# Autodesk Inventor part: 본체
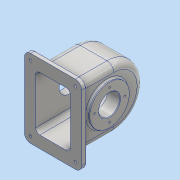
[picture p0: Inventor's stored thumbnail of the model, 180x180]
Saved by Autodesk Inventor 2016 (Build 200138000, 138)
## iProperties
Created: 2018-11
Part Number: 본체
Material: 알루미늄 6061
Document SubType Name: Modeling
Designer: user
Mass: 1091.9 g
Surface Area: 1182.65 cm^2
Volume: 404.407 cm^3
Density: 2.7 g/cm^3
Appearance: 알루미늄 - 평지
Author: user
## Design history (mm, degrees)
sketch "스케치1"
  geometry: L1 (55, 75)-(-55, 75); L2 (-55, 75)-(-55, -75); L3 (-55, -75)-(55, -75); L4 (55, -75)-(55, 75); L5 (55, 75)-(-55, -75); L6 (-55, 75)-(55, -75); 1 further point
  constraints: 12 end point, 2 midpoint, 2 parallel, 1 horizontal, 1 perpendicular
  dimensions: "d0" = 110 distance of L3.end L2.end; "d1" = 150 distance of L2.end L1.end
extrude "돌출1" new body sketch "스케치1" distance "d2" = 10; taper "d3" = 0 deg
sketch "스케치2"
  geometry: L1 (-38.5, -58)-(38.5, -58); L2 (38.5, -58)-(38.5, 58); L3 (38.5, 58)-(-38.5, 58); L4 (-38.5, 58)-(-38.5, -58); L5 (-38.5, -58)-(38.5, 58); L6 (38.5, -58)-(-38.5, 58); 1 further point
  constraints: 12 end point, 2 midpoint, 2 parallel, 1 horizontal, 1 perpendicular
  dimensions: "d4" = 77 distance of L3.end L2.end; "d5" = 116 distance of L2.end L1.end
extrude "돌출2" join sketch "스케치2" distance "d6" = 68; taper "d7" = 0 deg
sketch "스케치3"
  geometry: L1 (116, 68)-(0, 68) reference; L2 (0, 68)-(116, 68); A1 r 58 centre (58, 68) between (116, 68) and (0, 68); 1 further point
  constraints: 2 end point, 2 point on circle, 1 centre point, 1 collinear, 1 midpoint
extrude "돌출3" join sketch "스케치3" distance "d8" = 77; taper "d9" = 0 deg
feature "쉘1" dims "d10" = 6, "d11" = 10, "d12" = 5
sketch "스케치4"
  geometry: L1 (-17, -10)-(133, -10) reference; C1 r 38 at (58, 55); 2 further points
  constraints: 1 centre point, 1 midpoint, 1 vertical alignment
  dimensions: "d13" = 76 diameter of C1; "d14" = 65 distance from line of L1 C1.centre
extrude "돌출4" join sketch "스케치4" distance "d15" = 5; taper "d16" = 0 deg
sketch "스케치8"
  geometry: L1 (-17, -10)-(133, -10) reference; C1 r 38 at (58, 55); 2 further points
  constraints: 1 centre point, 1 midpoint, 1 vertical alignment
  dimensions: "d34" = 76 diameter of C1; "d35" = 65 distance from line of L1 C1.centre
extrude "돌출7" join sketch "스케치8" distance "d36" = 10; taper "d37" = 0 deg
sketch "스케치9"
  geometry: L1 (33.5, 104.747)-(33.5, 65); L2 (33.5, 65)-(19.5, 65); L3 (19.5, 65)-(19.5, 93); L4 (19.5, 93)-(33.5, 104.747); L5 (33.5, 130)-(33.5, 78) reference; L6 (43.5, 27)-(43.5, 103) reference; 1 further point
  constraints: 8 end point, 2 perpendicular, 1 collinear, 1 vertical
  dimensions: "d38" = 65 distance from line of point (0, 0) L2; "d39" = 24 distance between parallel lines of L6 L3; "d40" = 28 distance of L2.end L3.end; "d41" = 50 deg angle of L4 L3
revolve "회전1" sketch "스케치9" stored, may be unused: angle "d42" = 90 deg
sketch "스케치10"
  geometry: C1 r 38 at (0, 0) reference; C2 r 20 at (0, 0); 1 further point
  constraints: 1 centre point, 1 coincident
  dimensions: "d43" = 40 diameter of C2
extrude "돌출8" cut sketch "스케치10" stored distance "d44" = 10; taper "d45" = 0 deg
sketch "스케치11"
  geometry: C1 r 38 at (0, 0) reference; 2 further points
  constraints: 1 vertical alignment
  dimensions: "d46" = 29 distance of C1.centre point (0, 29)
hole "구멍2" sketch "스케치11" at (0, 29) diameter "d47" = 3.242; stored, may be unused: countersink angle "d51" = 90 deg, drill point angle "d53" = 118 deg; dims "d48" = 8, "d49" = 4, "d50" = 2, "d52" = 10
sketch "스케치12"
  geometry: C1 r 38 at (0, 0) reference; 2 further points
  constraints: 1 vertical alignment
  dimensions: "d57" = 29 distance of C1.centre point (0, 29)
hole "구멍3" sketch "스케치12" at (0, 29) diameter "d58" = 3.242; stored, may be unused: countersink angle "d62" = 90 deg, drill point angle "d64" = 118 deg; dims "d59" = 8, "d60" = 4, "d61" = 2, "d63" = 10
node "작업 평면1"
sketch "스케치13"
  geometry: C1 r 6 at (0, 0); 1 further point
  constraints: 1 centre point, 1 coincident
  dimensions: "d69" = 12 diameter of C1
extrude "돌출9" join sketch "스케치13" stored distance "d70" = 10; taper "d71" = 5 deg
fillet "모깎기1" dims "d79" = 12
sketch "스케치15"
  geometry: C1 r 6 at (43, 63); A1 r 12 centre (43, 63) between (55, 63) and (43, 75) reference; 1 further point
  constraints: 1 centre point, 1 coincident
  dimensions: "d80" = 12 diameter of C1
extrude "돌출10" cut sketch "스케치15" distance "d81" = 4; taper "d82" = 0 deg
sketch "스케치16"
  geometry: C1 r 6 at (0, 0) reference; C2 r 2.5 at (0, 0); 1 further point
  constraints: 1 centre point, 1 coincident
  dimensions: "d83" = 5 diameter of C2
extrude "돌출11" cut sketch "스케치16" stored distance "d84" = 0; taper "d85" = 0 deg
chamfer "모따기1" distance "d86" = 1; stored, may be unused: second distance "d87" = 2, angle "d88" = 45 deg
fillet "모깎기2" dims "d89" = 13
fillet "모깎기3" dims "d90" = 8
fillet "모깎기4" dims "d91" = 3
sketch "스케치17"
  geometry: L1 (-17.5, -78)-(-29.5, -78) reference; L2 (-13, 0)-(-13, -65) reference; 2 further points
  constraints: 1 other
  dimensions: "d92" = 40 distance from line of L1 point (25.5, -38); "d93" = 38.5 distance from line of L2 point (25.5, -38)
feature "엠보싱1" sketch "스케치17" dims "d0" = 110, "d1" = 150, "d94" = 0.5, "d95" = 0
sketch "스케치18"
  geometry: 2 further points
  constraints: 1 coincident
hole "구멍5" sketch "스케치18" at (0, 0) diameter "d96" = 4.459; stored, may be unused: countersink angle "d100" = 90 deg, drill point angle "d102" = 118 deg; dims "d97" = 20, "d98" = 4, "d99" = 2, "d101" = 20
fillet "모깎기5" dims "d103" = 3
node "솔리드1"
pattern_circular "원형 패턴2" dims angle "d55" = 360 deg
pattern_circular "원형 패턴3" dims angle "d66" = 360 deg
mirror "대칭1"
mirror "대칭2"
other parameters: "d68" = 142
